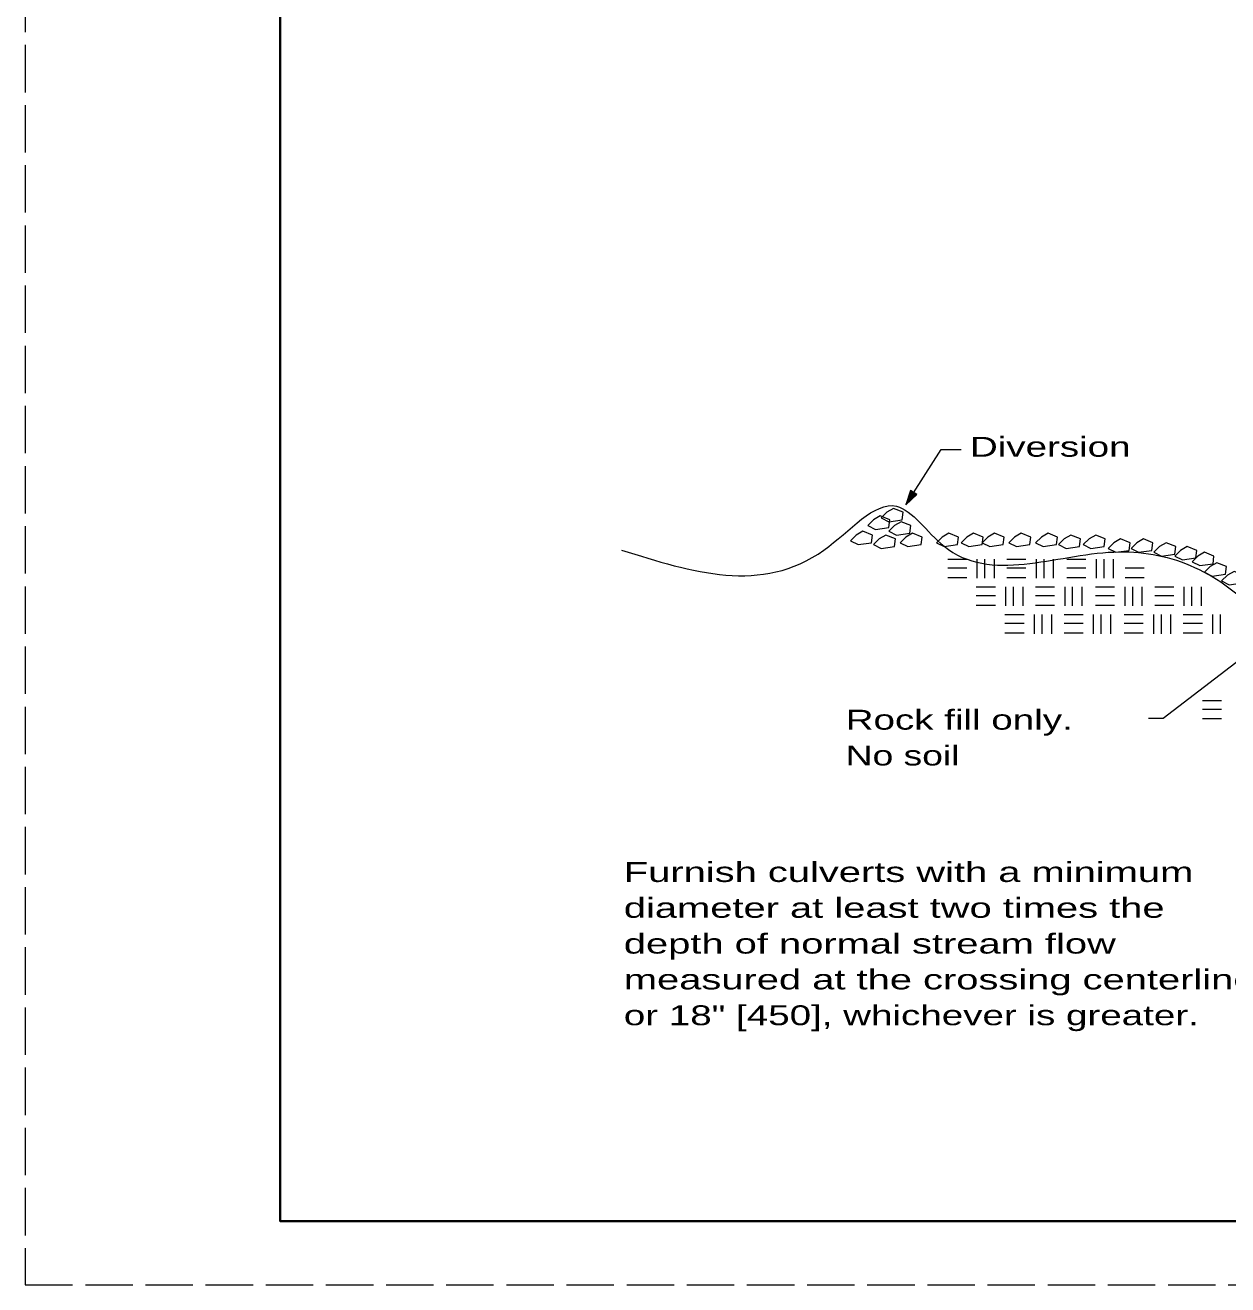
# Model space of a CAD drawing. Extents: x 1083.1 to 1117.1, y 719.4 to 741.4.
# Drawn here: x 1083.13 to 1092.56, y 719.35 to 729.24 of the extents above; entities that cross this region are included whole.
import ezdxf

# ---------------------------------------------------------------- set-up
doc = ezdxf.new("R2010")
doc.units = 0
doc.header["$LTSCALE"] = 0.062
doc.linetypes.add('LONG_DASHED', pattern=[7.5, 6, -1.5])
doc.layers.add('1', color=7, linetype='Continuous', lineweight=13)

msp = doc.modelspace()

# ---------------------------------------------------------------- hatches: boundary and pattern name
at = {"layer": '1'}
msp.add_hatch(color=256, dxfattribs=at).paths.add_polyline_path([(1090.075, 725.58742), (1090.03633, 725.47267), (1090.1245, 725.55575)])

# ---------------------------------------------------------------- linework, layer by layer
for p, q in [((1090.36558, 725.04692), (1090.51525, 725.04692)), ((1090.59767, 724.89717), (1090.59767, 725.04683)), ((1090.6575, 724.89717), (1090.6575, 725.04683)), ((1090.73233, 724.89717), (1090.73233, 725.04683)), ((1090.82967, 725.04692), (1090.97933, 725.04692)), ((1091.06175, 724.89717), (1091.06175, 725.04683)), ((1091.12158, 724.89717), (1091.12158, 725.04683)), ((1091.19642, 724.89717), (1091.19642, 725.04683)), ((1091.30117, 725.04692), (1091.45083, 725.04692)), ((1091.53325, 724.89717), (1091.53325, 725.04683)), ((1091.59308, 724.89717), (1091.59308, 725.04683)), ((1091.66792, 724.89717), (1091.66792, 725.04683)), ((1090.36558, 724.9795), (1090.51525, 724.9795)), ((1090.82967, 724.9795), (1090.97933, 724.9795)), ((1091.30117, 724.9795), (1091.45083, 724.9795)), ((1091.75775, 724.9795), (1091.90742, 724.9795)), ((1090.36558, 724.90458), (1090.51525, 724.90458)), ((1090.59017, 724.82975), (1090.73983, 724.82975)), ((1090.82225, 724.68), (1090.82225, 724.82967)), ((1090.82967, 724.90458), (1090.97933, 724.90458)), ((1090.88208, 724.68), (1090.88208, 724.82967)), ((1090.95692, 724.68), (1090.95692, 724.82967)), ((1091.05425, 724.82975), (1091.20392, 724.82975)), ((1091.28633, 724.68), (1091.28633, 724.82967)), ((1091.30117, 724.90458), (1091.45083, 724.90458)), ((1091.34617, 724.68), (1091.34617, 724.82967)), ((1091.421, 724.68), (1091.421, 724.82967)), ((1091.52575, 724.82975), (1091.67542, 724.82975)), ((1091.75775, 724.90458), (1091.90742, 724.90458)), ((1091.75783, 724.68), (1091.75783, 724.82967)), ((1091.81767, 724.68), (1091.81767, 724.82967)), ((1091.8925, 724.68), (1091.8925, 724.82967)), ((1091.98983, 724.82975), (1092.1395, 724.82975)), ((1092.22192, 724.68), (1092.22192, 724.82967)), ((1092.28175, 724.68), (1092.28175, 724.82967)), ((1092.35658, 724.68), (1092.35658, 724.82967)), ((1090.59017, 724.76233), (1090.73983, 724.76233)), ((1091.05425, 724.76233), (1091.20392, 724.76233)), ((1091.52575, 724.76233), (1091.67542, 724.76233)), ((1091.98983, 724.76233), (1092.1395, 724.76233)), ((1090.59017, 724.68742), (1090.73983, 724.68742)), ((1090.81475, 724.61258), (1090.96442, 724.61258)), ((1091.04683, 724.46283), (1091.04683, 724.6125)), ((1091.05425, 724.68742), (1091.20392, 724.68742)), ((1091.10667, 724.46283), (1091.10667, 724.6125)), ((1091.1815, 724.46283), (1091.1815, 724.6125)), ((1091.27883, 724.61258), (1091.4285, 724.61258)), ((1091.51092, 724.46283), (1091.51092, 724.6125)), ((1091.52575, 724.68742), (1091.67542, 724.68742)), ((1091.57075, 724.46283), (1091.57075, 724.6125)), ((1091.64558, 724.46283), (1091.64558, 724.6125)), ((1091.75033, 724.61258), (1091.9, 724.61258)), ((1091.98242, 724.46283), (1091.98242, 724.6125)), ((1091.98983, 724.68742), (1092.1395, 724.68742)), ((1092.04225, 724.46283), (1092.04225, 724.6125)), ((1092.11708, 724.46283), (1092.11708, 724.6125)), ((1092.21442, 724.61258), (1092.36408, 724.61258)), ((1092.4465, 724.46283), (1092.4465, 724.6125)), ((1092.50633, 724.46283), (1092.50633, 724.6125)), ((1090.81475, 724.54517), (1090.96442, 724.54517)), ((1091.27883, 724.54517), (1091.4285, 724.54517)), ((1091.75033, 724.54517), (1091.9, 724.54517)), ((1092.21442, 724.54517), (1092.36408, 724.54517)), ((1090.81475, 724.47025), (1090.96442, 724.47025)), ((1091.27883, 724.47025), (1091.4285, 724.47025)), ((1091.75033, 724.47025), (1091.9, 724.47025)), ((1092.87825, 724.42917), (1092.05692, 723.7965)), ((1092.21442, 724.47025), (1092.36408, 724.47025)), ((1092.36408, 723.93867), (1092.51375, 723.93867)), ((1092.36408, 723.87125), (1092.51375, 723.87125)), ((1092.05692, 723.7965), (1091.94192, 723.7965)), ((1092.36408, 723.79633), (1092.51375, 723.79633))]:
    msp.add_line(p, q, dxfattribs=at)
at = {"layer": '1', "linetype": 'LONG_DASHED'}
msp.add_lwpolyline([(1083.12642, 719.35408), (1117.12642, 719.35408), (1117.12642, 741.35408), (1083.12642, 741.35408)], close=True, dxfattribs=at)
at = {"layer": '1', "lineweight": 25}
msp.add_lwpolyline([(1116.62642, 719.85408), (1085.12642, 719.85408), (1085.12642, 740.85408)], dxfattribs=at)
at = {"layer": '1', "lineweight": 40}
for points in [[(1116.62642, 719.85408), (1085.12642, 719.85408), (1085.12642, 740.85408), (1116.62642, 740.85408)], [(1116.62642, 719.85408), (1085.12642, 719.85408), (1085.12642, 740.85408)]]:
    msp.add_lwpolyline(points, dxfattribs=at)
at = {"layer": '1'}
msp.add_lwpolyline([(1090.03633, 725.47267), (1090.31558, 725.90817), (1090.47167, 725.90817)], dxfattribs=at)
for points in [[(1090.075, 725.58742), (1090.03633, 725.47267), (1090.1245, 725.55575)], [(1089.94033, 725.446), (1089.88792, 725.416), (1089.843, 725.37108), (1089.90283, 725.34117), (1090.00767, 725.35617), (1090.01517, 725.416)], [(1089.83558, 725.38608), (1089.78317, 725.35608), (1089.73825, 725.31117), (1089.79808, 725.28125), (1089.90292, 725.29625), (1089.91042, 725.35608)], [(1090.00025, 725.34117), (1089.94783, 725.31117), (1089.90292, 725.26625), (1089.96275, 725.23633), (1090.06758, 725.25133), (1090.07508, 725.31117)], [(1089.70083, 725.26625), (1089.64842, 725.23625), (1089.6035, 725.19133), (1089.66333, 725.16142), (1089.76817, 725.17642), (1089.77567, 725.23625)], [(1089.8805, 725.23633), (1089.82808, 725.20633), (1089.78317, 725.16142), (1089.843, 725.1315), (1089.94783, 725.1465), (1089.95533, 725.20633)], [(1090.09, 725.25125), (1090.03758, 725.22125), (1089.99267, 725.17633), (1090.0525, 725.14642), (1090.15733, 725.16142), (1090.16483, 725.22125)], [(1090.3745, 725.25125), (1090.32208, 725.22125), (1090.27717, 725.17633), (1090.337, 725.14642), (1090.44183, 725.16142), (1090.44933, 725.22125)], [(1090.56908, 725.25125), (1090.51667, 725.22125), (1090.47175, 725.17633), (1090.53158, 725.14642), (1090.63642, 725.16142), (1090.64392, 725.22125)], [(1090.73375, 725.25125), (1090.68133, 725.22125), (1090.63642, 725.17633), (1090.69625, 725.14642), (1090.80108, 725.16142), (1090.80858, 725.22125)], [(1090.94333, 725.25125), (1090.89092, 725.22125), (1090.846, 725.17633), (1090.90583, 725.14642), (1091.01067, 725.16142), (1091.01817, 725.22125)], [(1091.15292, 725.25125), (1091.1005, 725.22125), (1091.05558, 725.17633), (1091.11542, 725.14642), (1091.22025, 725.16142), (1091.22775, 725.22125)], [(1091.33258, 725.23633), (1091.28017, 725.20633), (1091.23525, 725.16142), (1091.29508, 725.1315), (1091.39992, 725.1465), (1091.40742, 725.20633)], [(1091.52717, 725.23633), (1091.47475, 725.20633), (1091.42983, 725.16142), (1091.48967, 725.1315), (1091.5945, 725.1465), (1091.602, 725.20633)], [(1091.72175, 725.20633), (1091.66933, 725.17633), (1091.62442, 725.13142), (1091.68425, 725.1015), (1091.78908, 725.1165), (1091.79658, 725.17633)], [(1091.90142, 725.20633), (1091.849, 725.17633), (1091.80408, 725.13142), (1091.86392, 725.1015), (1091.96875, 725.1165), (1091.97625, 725.17633)], [(1092.08108, 725.17642), (1092.02867, 725.14642), (1091.98375, 725.1015), (1092.04358, 725.07158), (1092.14842, 725.08658), (1092.15592, 725.14642)], [(1092.24575, 725.14642), (1092.19333, 725.11642), (1092.14842, 725.0715), (1092.20825, 725.04158), (1092.31308, 725.05658), (1092.32058, 725.11642)], [(1092.38042, 725.1015), (1092.328, 725.0715), (1092.28308, 725.02658), (1092.34292, 724.99667), (1092.44775, 725.01167), (1092.45525, 725.0715)], [(1092.47767, 725.01917), (1092.42525, 724.98917), (1092.38033, 724.94425), (1092.44017, 724.91433), (1092.545, 724.92933), (1092.5525, 724.98917)], [(1092.61242, 724.95175), (1092.56, 724.92175), (1092.51508, 724.87683), (1092.57492, 724.84692), (1092.67975, 724.86192), (1092.68725, 724.92175)]]:
    msp.add_lwpolyline(points, close=True, dxfattribs=at)
msp.add_spline([(1087.80692, 725.11858), (1089.39375, 725.11858), (1089.96258, 725.463), (1090.33683, 725.1485), (1091.66917, 725.10358), (1092.268, 724.99875), (1092.77692, 724.63933), (1093.19608, 724.14517), (1093.89967, 723.77075), (1097.64217, 723.80075), (1097.732, 723.80075), (1098.37575, 724.30992), (1098.75, 724.72925), (1099.28892, 725.05867), (1101.53442, 725.10358), (1102.01342, 725.1485), (1102.56733, 725.59783), (1103.04642, 725.1635), (1104.0045, 725.13358)], degree=3, dxfattribs=at)

# ---------------------------------------------------------------- texts
for s, width, p in [('Diversion', 1.45, (1090.54008, 725.85117)), ('Rock fill only.', 1.45, (1089.56508, 723.70975)), ('No soil', 1.4, (1089.56508, 723.42875)), ('Furnish culverts with a minimum', 1.5, (1087.82408, 722.51483)), ('diameter at least two times the ', 1.5, (1087.82408, 722.23383)), ('depth of normal stream flow ', 1.5, (1087.82408, 721.95283)), ('measured at the crossing centerline', 1.5, (1087.82408, 721.67183)), ('or 18" [450], whichever is greater.', 1.45, (1087.82408, 721.39083))]:
    msp.add_text(s, height=0.156, dxfattribs=dict(at, width=width)).set_placement(p)

doc.saveas('drawing.dxf')
